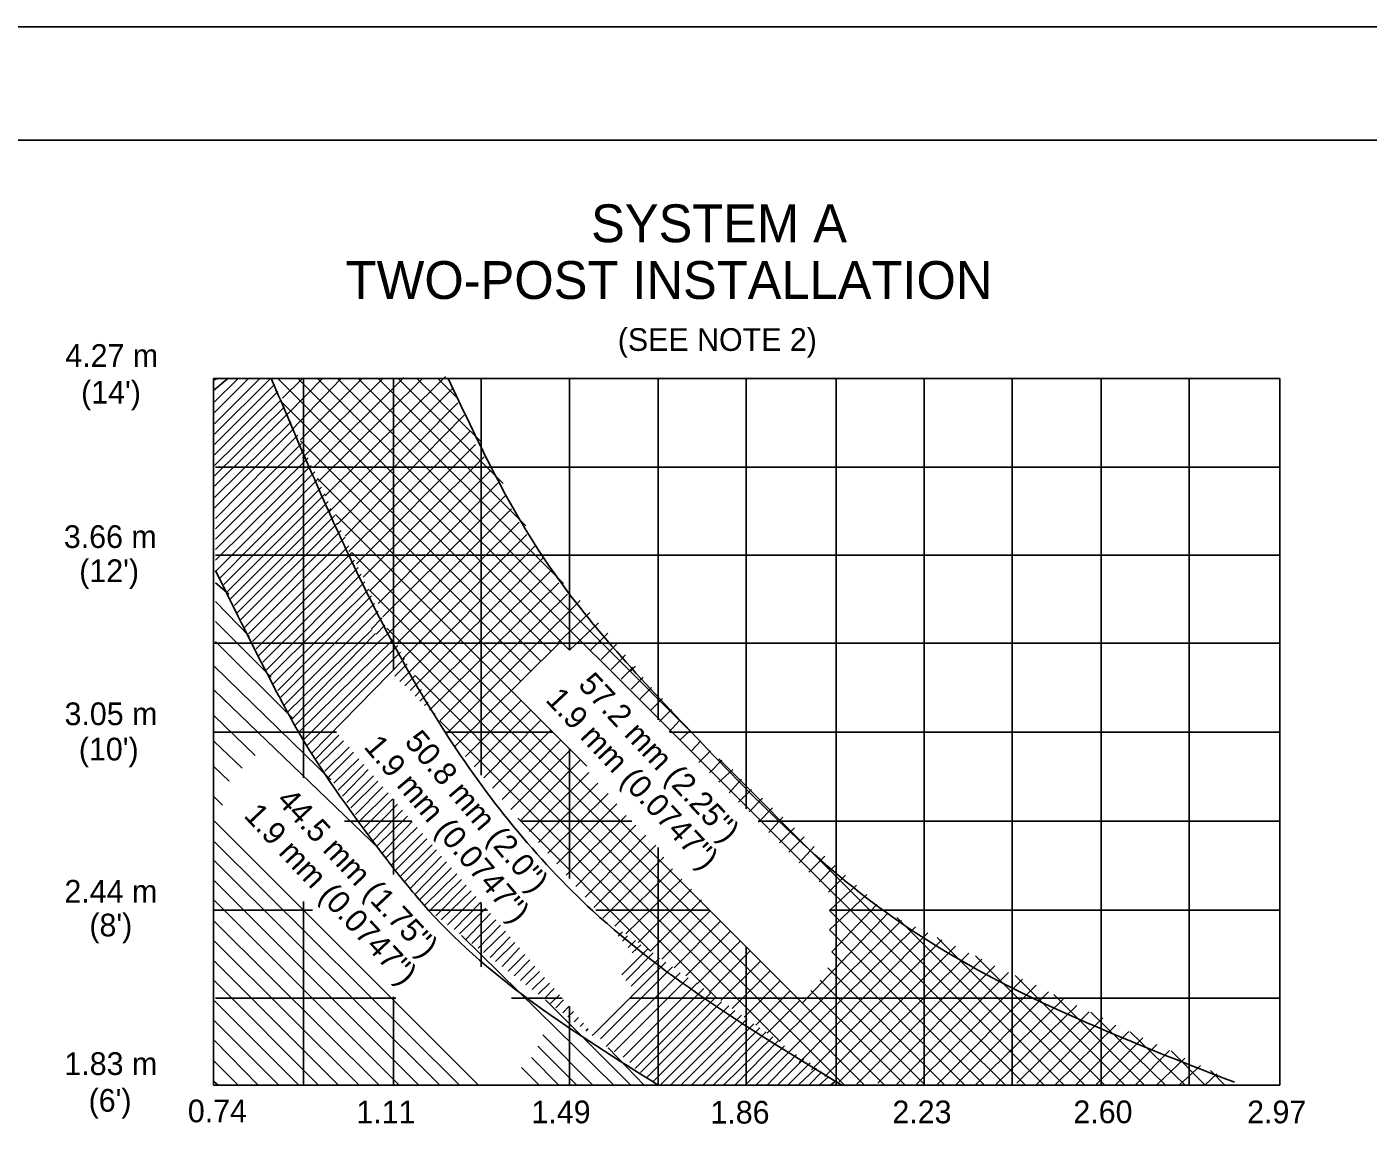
# Model space of a CAD drawing. Extents: x 644358 to 648627, y 294594 to 295782.
# Drawn here: x 645568.3 to 645745.5, y 295636.1 to 295781.6 of the extents above; entities that cross this region are included whole.
import ezdxf

# ---------------------------------------------------------------- set-up
doc = ezdxf.new("R2010")
doc.units = 0
for name, color, linetype in [('1', 7, 'Continuous'), ('10', 7, 'Continuous'), ('2', 7, 'Continuous'), ('4', 7, 'Continuous'), ('PLT-BNDY', 7, 'Continuous')]:
    doc.layers.add(name, color=color, linetype=linetype)

msp = doc.modelspace()

# ---------------------------------------------------------------- linework, layer by layer
at = {"layer": '1'}
msp.add_line((645239.31, 295766.63), (646025.31, 295766.63), dxfattribs=at)
at = {"layer": '10'}
for p, q in [((645592.94, 295734.93), (645593.44, 295735.18)), ((645592.94, 295733.56), (645594.81, 295735.18)), ((645593.06, 295732.06), (645596.19, 295735.18)), ((645593.06, 295730.68), (645597.56, 295735.18)), ((645593.06, 295729.18), (645599.06, 295735.18)), ((645593.06, 295727.81), (645600.44, 295735.18)), ((645637.51, 295699.12), (645601.44, 295735.18)), ((645602.06, 295732.56), (645604.69, 295735.18)), ((645602.69, 295730.43), (645607.31, 295735.18)), ((645603.31, 295728.43), (645609.69, 295735.06)), ((645639.97, 295699.28), (645604.06, 295735.18)), ((645604.44, 295727.06), (645612.56, 295735.18)), ((645604.69, 295724.68), (645615.31, 295735.18)), ((645606.19, 295723.43), (645618.06, 295735.31)), ((645650.65, 295691.28), (645606.69, 295735.18)), ((645606.81, 295721.56), (645620.56, 295735.18)), ((645607.69, 295719.68), (645623.56, 295735.43)), ((645655.79, 295688.71), (645609.31, 295735.18)), ((645639.19, 295708.06), (645612.06, 295735.18)), ((645634.19, 295715.68), (645614.69, 295735.18)), ((645631.19, 295721.31), (645617.31, 295735.18)), ((645628.31, 295726.81), (645619.81, 295735.18)), ((645625.31, 295732.43), (645622.56, 295735.18)), ((645593.06, 295726.43), (645600.94, 295734.31)), ((645593.06, 295725.06), (645601.44, 295733.43)), ((645608.19, 295717.56), (645624.44, 295733.81)), ((645593.06, 295723.68), (645601.81, 295732.31)), ((645593.06, 295722.31), (645602.31, 295731.43)), ((645636.19, 295697.81), (645602.06, 295731.93)), ((645609.31, 295715.93), (645625.19, 295731.93)), ((645593.06, 295720.93), (645602.81, 295730.56)), ((645593.06, 295719.43), (645603.19, 295729.43)), ((645610.31, 295714.31), (645626.06, 295730.31)), ((645593.06, 295718.06), (645603.56, 295728.56)), ((645593.19, 295716.68), (645604.06, 295727.68)), ((645610.81, 295712.31), (645626.81, 295728.18)), ((645593.19, 295715.31), (645604.56, 295726.56)), ((645593.19, 295713.93), (645604.94, 295725.68)), ((645634.87, 295696.5), (645604.44, 295726.93)), ((645611.81, 295710.68), (645627.56, 295726.43)), ((645593.19, 295712.56), (645605.44, 295724.68)), ((645612.69, 295708.93), (645628.69, 295724.81)), ((645593.19, 295711.18), (645605.81, 295723.68)), ((645593.19, 295709.68), (645606.31, 295722.81)), ((645613.69, 295707.18), (645629.56, 295723.06)), ((645593.81, 295708.81), (645606.69, 295721.81)), ((645594.31, 295707.93), (645607.19, 295720.81)), ((645633.51, 295695.16), (645606.69, 295721.93)), ((645614.69, 295705.43), (645630.56, 295721.43)), ((645594.69, 295706.93), (645607.69, 295719.93)), ((645595.19, 295706.06), (645608.06, 295718.93)), ((645615.31, 295703.68), (645631.44, 295719.68)), ((645595.69, 295705.18), (645608.44, 295717.93)), ((645596.06, 295704.18), (645608.94, 295717.06)), ((645642.24, 295683.95), (645609.06, 295717.18)), ((645615.81, 295701.31), (645632.31, 295717.93)), ((645596.56, 295703.31), (645609.31, 295716.06)), ((645597.06, 295702.31), (645609.81, 295715.06)), ((645617.19, 295700.18), (645633.31, 295716.18)), ((645597.56, 295701.43), (645610.31, 295714.18)), ((645617.53, 295695.15), (645635.56, 295713.18)), ((645617.94, 295698.18), (645634.31, 295714.56)), ((645598.06, 295700.43), (645610.81, 295713.06)), ((645598.56, 295699.43), (645611.19, 295712.18)), ((645681.56, 295641.81), (645611.19, 295712.18)), ((645618.92, 295693.92), (645636.44, 295711.43)), ((645598.94, 295698.56), (645611.56, 295711.18)), ((645599.44, 295697.68), (645612.06, 295710.18)), ((645620.17, 295692.55), (645637.56, 295709.81)), ((645594.94, 295706.68), (645593.19, 295708.18)), ((645599.94, 295696.68), (645612.44, 295709.31)), ((645600.31, 295695.81), (645612.94, 295708.31)), ((645621.46, 295691.34), (645638.56, 295708.18)), ((645600.81, 295694.81), (645613.44, 295707.31)), ((645601.44, 295693.93), (645613.81, 295706.43)), ((645678.94, 295641.81), (645613.56, 295707.18)), ((645633.14, 295700.18), (645639.69, 295706.68)), ((645597.69, 295701.06), (645593.19, 295705.68)), ((645601.81, 295693.06), (645614.19, 295705.43)), ((645602.31, 295692.06), (645614.69, 295704.43)), ((645635.69, 295700.18), (645641.35, 295705.84)), ((645600.56, 295695.68), (645593.19, 295703.06)), ((645613.81, 295702.1), (645615.19, 295703.56)), ((645614.4, 295701.4), (645615.56, 295702.56)), ((645638.36, 295700.18), (645642.63, 295704.23)), ((645639.97, 295699.28), (645643.79, 295702.89)), ((645602.81, 295691.18), (645613.87, 295702.02)), ((645603.31, 295690.18), (645614.35, 295701.46)), ((645615.06, 295700.62), (645616.06, 295701.56)), ((645676.31, 295641.81), (645615.81, 295702.18)), ((645642.71, 295699.21), (645645.02, 295701.51)), ((645603.44, 295690.18), (645593.19, 295700.43)), ((645603.69, 295689.31), (645615.03, 295700.65)), ((645604.19, 295688.43), (645616.7, 295700.7)), ((645604.81, 295687.43), (645617.26, 295699.88)), ((645605.31, 295686.68), (645617.64, 295699.01)), ((645622.81, 295689.93), (645633.14, 295700.18)), ((645623.81, 295688.31), (645635.69, 295700.18)), ((645624.81, 295686.56), (645638.59, 295700.18)), ((645644.16, 295698.05), (645645.76, 295699.65)), ((645645.31, 295699.18), (645646.19, 295700.06)), ((645608.43, 295682.12), (645592.94, 295697.23)), ((645605.94, 295685.68), (645618.16, 295698.15)), ((645616.9, 295695.84), (645618.52, 295697.46)), ((645645.47, 295696.73), (645647.08, 295698.34)), ((645646.63, 295697.87), (645647.37, 295698.66)), ((645618.19, 295694.55), (645619.57, 295695.93)), ((645667.75, 295647.63), (645619.57, 295695.93)), ((645646.79, 295695.42), (645648.39, 295697.02)), ((645648, 295696.5), (645648.67, 295697.17)), ((645648.1, 295694.11), (645649.7, 295695.71)), ((645593.02, 295694), (645614.84, 295672.96)), ((645619.55, 295693.19), (645620.41, 295694.06)), ((645649.2, 295692.73), (645650.81, 295694.33)), ((645620.8, 295691.95), (645621.27, 295692.42)), ((645626.23, 295685.23), (645633.56, 295692.64)), ((645650.65, 295691.28), (645652.26, 295692.88)), ((645593.02, 295690.58), (645598.42, 295685.37)), ((645622.03, 295690.72), (645622.22, 295690.91)), ((645627.38, 295683.87), (645634.85, 295691.35)), ((645700.19, 295641.81), (645650.65, 295691.28)), ((645651.85, 295689.84), (645653.44, 295691.43)), ((645659.44, 295653.31), (645622.81, 295689.93)), ((645628.64, 295682.39), (645636.18, 295690.02)), ((645629.79, 295681.04), (645637.48, 295688.72)), ((645653.11, 295688.49), (645654.44, 295689.93)), ((645654.54, 295687.39), (645655.81, 295688.56)), ((645593.02, 295687.22), (645596.71, 295683.66)), ((645606.44, 295684.93), (645609.49, 295688.05)), ((645606.98, 295684.23), (645610.12, 295687.3)), ((645631.05, 295679.55), (645638.81, 295687.39)), ((645656.02, 295685.91), (645657.31, 295687.31)), ((645607.65, 295683.28), (645610.84, 295686.46)), ((645608.17, 295682.55), (645611.41, 295685.78)), ((645608.82, 295681.69), (645612.13, 295684.93)), ((645632.2, 295678.2), (645640.1, 295686.1)), ((645657.06, 295684.43), (645658.61, 295685.98)), ((645702.69, 295641.81), (645659.69, 295684.93)), ((645593.02, 295683.85), (645594.99, 295681.95)), ((645609.41, 295680.78), (645612.79, 295684.16)), ((645609.98, 295679.98), (645613.35, 295683.5)), ((645633.46, 295676.71), (645641.43, 295684.76)), ((645634.67, 295675.29), (645642.5, 295683.12)), ((645658.44, 295683.06), (645660.1, 295684.73)), ((645659.69, 295681.81), (645661.53, 295683.48)), ((645610.53, 295679.15), (645614.05, 295682.67)), ((645611.06, 295678.43), (645614.66, 295681.95)), ((645635.87, 295673.87), (645643.69, 295681.69)), ((645661.06, 295680.43), (645662.7, 295682.23)), ((645593.02, 295679.87), (645594.12, 295678.8)), ((645611.67, 295677.54), (645615.31, 295681.19)), ((645612.24, 295676.73), (645615.99, 295680.4)), ((645612.83, 295675.83), (645616.63, 295679.63)), ((645637.08, 295672.45), (645645.05, 295680.34)), ((645662.31, 295679.18), (645664, 295680.88)), ((645663.69, 295677.93), (645665.46, 295679.71)), ((645613.43, 295675.06), (645617.22, 295678.94)), ((645614.02, 295674.14), (645617.91, 295678.13)), ((645638.28, 295671.03), (645646.21, 295678.95)), ((645664.94, 295676.56), (645666.8, 295678.42)), ((645627.94, 295641.81), (645593.06, 295676.68)), ((645614.54, 295673.41), (645618.58, 295677.35)), ((645615.24, 295672.49), (645619.18, 295676.64)), ((645650.66, 295659.49), (645633.15, 295677.07)), ((645639.54, 295669.54), (645647.44, 295677.44)), ((645640.81, 295668.06), (645648.74, 295676.14)), ((645666.31, 295675.18), (645668.16, 295677.21)), ((645615.71, 295671.83), (645619.84, 295675.86)), ((645616.38, 295670.88), (645620.54, 295675.04)), ((645616.92, 295670.17), (645621.11, 295674.36)), ((645642.01, 295666.64), (645650.05, 295674.83)), ((645667.69, 295673.81), (645669.68, 295675.8)), ((645668.94, 295672.56), (645670.98, 295674.6)), ((645625.44, 295641.81), (645593.06, 295673.93)), ((645617.61, 295669.36), (645621.8, 295673.55)), ((645618.17, 295668.67), (645622.37, 295672.87)), ((645643.16, 295665.28), (645651.38, 295673.5)), ((645670.31, 295671.18), (645672.29, 295673.34)), ((645622.81, 295641.81), (645593.06, 295671.43)), ((645618.91, 295667.78), (645623.07, 295672.05)), ((645619.55, 295667.04), (645623.7, 295671.31)), ((645644.37, 295663.86), (645652.42, 295671.92)), ((645671.56, 295669.93), (645673.69, 295672.06)), ((645672.94, 295668.68), (645675.07, 295670.82)), ((645620.16, 295666.29), (645624.38, 295670.51)), ((645620.79, 295665.54), (645625.06, 295669.7)), ((645621.56, 295664.93), (645625.69, 295668.96)), ((645645.93, 295662.8), (645653.59, 295670.39)), ((645647.4, 295661.77), (645654.79, 295669.01)), ((645674.19, 295667.31), (645676.41, 295669.54)), ((645620.06, 295641.81), (645593.06, 295668.81)), ((645622.31, 295664.18), (645626.33, 295668.21)), ((645623.01, 295663.63), (645626.96, 295667.48)), ((645649.02, 295660.64), (645656.09, 295667.71)), ((645674.3, 295664.89), (645677.88, 295668.21)), ((645617.44, 295641.81), (645593.06, 295666.18)), ((645623.86, 295662.98), (645627.6, 295666.72)), ((645624.71, 295662.34), (645628.24, 295665.96)), ((645650.63, 295659.51), (645657.42, 295666.29)), ((645674.3, 295662.32), (645679.23, 295666.97)), ((645674.6, 295659.39), (645680.56, 295665.68)), ((645625.43, 295661.78), (645628.91, 295665.18)), ((645626.32, 295661.1), (645629.52, 295664.46)), ((645627.06, 295660.53), (645630.22, 295663.63)), ((645652.17, 295658.43), (645658.53, 295664.84)), ((645670.72, 295652.65), (645682.06, 295664.56)), ((645671.81, 295651.56), (645683.83, 295663.57)), ((645697.56, 295641.81), (645674.3, 295664.89)), ((645705.31, 295641.81), (645683.19, 295663.93)), ((645614.81, 295641.81), (645593.06, 295663.43)), ((645627.88, 295659.9), (645630.83, 295662.92)), ((645628.62, 295659.34), (645631.49, 295662.14)), ((645646.37, 295661.5), (645646.95, 295662.07)), ((645653.79, 295657.3), (645659.9, 295663.47)), ((645655.33, 295656.22), (645661.21, 295662.16)), ((645673.09, 295650.28), (645685.66, 295662.7)), ((645694.81, 295641.81), (645674.3, 295662.32)), ((645674.42, 295648.95), (645687.28, 295661.91)), ((645612.19, 295641.81), (645593.06, 295660.81)), ((645645.81, 295641.81), (645625.69, 295661.59)), ((645629.5, 295658.67), (645632.11, 295661.41)), ((645630.17, 295658.15), (645632.75, 295660.65)), ((645646.95, 295660.82), (645647.64, 295661.51)), ((645648.67, 295660.89), (645647.69, 295659.98)), ((645648.25, 295659.29), (645649.39, 295660.34)), ((645656.82, 295655.18), (645662.53, 295660.84)), ((645671.94, 295643.81), (645689.13, 295661)), ((645673.69, 295642.93), (645690.94, 295660.18)), ((645708.06, 295641.81), (645688.55, 295661.32)), ((645631.05, 295657.48), (645633.37, 295659.92)), ((645631.86, 295656.86), (645634.08, 295659.08)), ((645632.64, 295656.26), (645634.71, 295658.34)), ((645646.87, 295656.37), (645650.34, 295659.84)), ((645647.39, 295655.64), (645651.01, 295659.26)), ((645648.12, 295654.87), (645651.83, 295658.58)), ((645658.42, 295654.06), (645663.84, 295659.53)), ((645692.19, 295641.81), (645674.6, 295659.39)), ((645675.56, 295642.18), (645692.74, 295659.22)), ((645677.94, 295641.93), (645694.43, 295658.43)), ((645710.69, 295641.81), (645693.62, 295658.88)), ((645609.44, 295641.81), (645593.06, 295658.18)), ((645633.49, 295655.61), (645635.4, 295657.53)), ((645634.21, 295655.05), (645636.01, 295656.81)), ((645643.14, 295648.51), (645652.68, 295658.05)), ((645644.04, 295647.92), (645653.56, 295657.43)), ((645644.82, 295646.89), (645654.58, 295656.65)), ((645659.97, 295652.97), (645665.19, 295658.18)), ((645661.43, 295651.92), (645666.47, 295656.9)), ((645689.56, 295641.81), (645674.08, 295657.29)), ((645680.69, 295642.06), (645696.17, 295657.55)), ((645683.19, 295641.93), (645697.95, 295656.7)), ((645606.81, 295641.81), (645593.06, 295655.56)), ((645635.04, 295654.42), (645636.67, 295656.04)), ((645635.82, 295653.82), (645637.3, 295655.29)), ((645645.85, 295646.21), (645655.62, 295655.98)), ((645647.05, 295645.48), (645656.82, 295655.25)), ((645663.04, 295650.79), (645667.81, 295655.56)), ((645686.94, 295641.81), (645673.06, 295655.67)), ((645685.81, 295641.93), (645699.82, 295655.8)), ((645688.56, 295641.93), (645701.62, 295654.99)), ((645713.31, 295641.81), (645698.82, 295656.3)), ((645604.19, 295641.81), (645593.06, 295652.93)), ((645636.6, 295653.22), (645637.93, 295654.55)), ((645648.06, 295641.81), (645636.8, 295653.07)), ((645637.45, 295652.57), (645638.62, 295653.74)), ((645638.16, 295652.03), (645639.19, 295653.06)), ((645647.93, 295644.81), (645657.7, 295654.57)), ((645648.63, 295644.01), (645658.58, 295653.95)), ((645649.34, 295643.46), (645659.33, 295653.46)), ((645664.59, 295649.71), (645669.12, 295654.25)), ((645666.07, 295648.68), (645670.4, 295652.97)), ((645684.31, 295641.81), (645671.85, 295654.3)), ((645690.94, 295641.81), (645703.24, 295654.11)), ((645693.56, 295641.81), (645705.19, 295653.14)), ((645715.94, 295641.81), (645703.96, 295653.79)), ((645639.06, 295651.34), (645639.91, 295652.22)), ((645639.74, 295650.82), (645640.48, 295651.54)), ((645650.19, 295642.81), (645660.06, 295652.82)), ((645650.94, 295642.18), (645661.03, 295652.27)), ((645651.94, 295641.81), (645661.8, 295651.67)), ((645667.68, 295647.55), (645671.75, 295651.62)), ((645696.31, 295641.93), (645707, 295652.32)), ((645699.06, 295642.06), (645708.62, 295651.47)), ((645718.69, 295641.81), (645708.82, 295651.45)), ((645601.56, 295641.81), (645593.06, 295650.31)), ((645640.59, 295650.17), (645641.17, 295650.73)), ((645641.39, 295649.55), (645641.81, 295649.98)), ((645653.31, 295641.81), (645662.7, 295651.06)), ((645654.69, 295641.81), (645663.45, 295650.57)), ((645656.06, 295641.81), (645664.31, 295649.91)), ((645657.56, 295641.81), (645665.1, 295649.35)), ((645668.31, 295645.56), (645673.09, 295650.28)), ((645701.56, 295641.81), (645710.44, 295650.68)), ((645704.06, 295641.81), (645712.15, 295649.74)), ((645598.81, 295641.81), (645593.06, 295647.68)), ((645643.06, 295641.81), (645636.45, 295648.45)), ((645642.14, 295648.98), (645642.43, 295649.25)), ((645642.97, 295648.34), (645643.09, 295648.47)), ((645658.94, 295641.81), (645665.94, 295648.82)), ((645660.31, 295641.81), (645666.82, 295648.16)), ((645661.81, 295641.81), (645667.51, 295647.65)), ((645670.31, 295644.81), (645674.42, 295648.95)), ((645706.81, 295641.81), (645713.87, 295648.87)), ((645709.44, 295641.81), (645715.69, 295648.06)), ((645721.31, 295641.81), (645714.05, 295648.84)), ((645640.94, 295641.81), (645635.79, 295646.96)), ((645649.83, 295641.81), (645645.08, 295646.73)), ((645663.19, 295641.81), (645668.38, 295647)), ((645666.06, 295641.81), (645669.96, 295645.86)), ((645712.06, 295641.81), (645717.57, 295647.15)), ((645714.72, 295641.84), (645719.25, 295646.37)), ((645719.44, 295646.31), (645723.94, 295641.81)), ((645596.19, 295641.81), (645592.94, 295645.06)), ((645635.94, 295641.81), (645633.62, 295644.12)), ((645638.56, 295641.81), (645634.93, 295645.44)), ((645664.56, 295641.81), (645668.44, 295645.68)), ((645667.44, 295641.81), (645670.9, 295645.27)), ((645668.81, 295641.81), (645671.75, 295644.75)), ((645670.19, 295641.81), (645672.56, 295644.04)), ((645717.57, 295641.83), (645721.27, 295645.35)), ((645720.57, 295641.83), (645723.32, 295644.4)), ((645593.56, 295641.81), (645592.94, 295642.31)), ((645671.56, 295641.81), (645673.31, 295643.56)), ((645672.94, 295641.81), (645674.22, 295642.93)), ((645674.44, 295641.81), (645675.16, 295642.35)), ((645723.9, 295641.81), (645725.5, 295643.3)), ((645726.56, 295641.81), (645724.64, 295643.73)), ((645675.81, 295641.81), (645675.81, 295641.81))]:
    msp.add_line(p, q, dxfattribs=at)
at = {"layer": '2'}
for p, q in [((645733.81, 295735.18), (645592.94, 295735.18)), ((645592.94, 295688.43), (645592.94, 295735.18)), ((645604.81, 295682.41), (645604.81, 295735.18)), ((645616.69, 295696.65), (645616.69, 295735.18)), ((645628.31, 295682.77), (645628.31, 295735.18)), ((645639.94, 295699.31), (645639.94, 295735.18)), ((645651.69, 295690.07), (645651.69, 295735.18)), ((645663.31, 295678.29), (645663.31, 295735.18)), ((645675.19, 295641.81), (645675.19, 295735.18)), ((645686.81, 295641.81), (645686.81, 295735.18)), ((645698.44, 295641.81), (645698.44, 295735.18)), ((645710.19, 295641.81), (645710.19, 295735.18)), ((645721.81, 295641.81), (645721.81, 295735.18)), ((645733.81, 295641.81), (645733.81, 295735.18)), ((645733.69, 295723.43), (645593.19, 295723.43)), ((645733.69, 295711.81), (645593.19, 295711.81)), ((645644.31, 295700.18), (645592.94, 295700.18)), ((645733.69, 295700.18), (645641.73, 295700.18)), ((645592.94, 295641.81), (645592.94, 295688.43)), ((645609.16, 295688.43), (645592.94, 295688.43)), ((645637.76, 295688.43), (645623.51, 295688.43)), ((645733.69, 295688.43), (645653.21, 295688.43)), ((645639.94, 295669.08), (645639.94, 295686.26)), ((645616.69, 295669.63), (645616.69, 295679.57)), ((645619.14, 295676.68), (645610.22, 295676.68)), ((645648.2, 295676.68), (645633.48, 295676.68)), ((645733.69, 295676.68), (645664.87, 295676.68)), ((645651.69, 295653.31), (645651.69, 295673.19)), ((645604.81, 295641.81), (645604.81, 295666.06)), ((645628.31, 295657.43), (645628.31, 295665.88)), ((645606, 295664.93), (645592.94, 295664.93)), ((645629.11, 295664.93), (645621.32, 295664.93)), ((645658.44, 295664.93), (645643.46, 295664.93)), ((645733.69, 295664.93), (645674.3, 295664.93)), ((645663.31, 295641.81), (645663.31, 295660.06)), ((645617, 295653.31), (645593.19, 295653.31)), ((645638.98, 295653.31), (645632.28, 295653.31)), ((645733.78, 295653.31), (645647.94, 295653.31)), ((645651.69, 295641.81), (645651.69, 295653.31)), ((645639.94, 295641.81), (645639.94, 295652.19)), ((645639.94, 295641.81), (645592.94, 295641.81)), ((645733.81, 295641.81), (645639.94, 295641.81))]:
    msp.add_line(p, q, dxfattribs=at)
at = {"layer": '4'}
for p, q in [((645600.94, 295735.18), (645600.94, 295735.18)), ((645623.94, 295735.18), (645623.94, 295735.18)), ((645610.81, 295711.81), (645610.81, 295711.81)), ((645636.31, 295711.81), (645636.31, 295711.81)), ((645623.44, 295688.56), (645623.44, 295688.56)), ((645655.94, 295688.56), (645655.94, 295688.56)), ((645643.06, 295664.81), (645643.06, 295664.81)), ((645681.69, 295664.68), (645681.69, 295664.68)), ((645616.69, 295641.81), (645616.69, 295653.45)), ((645676.06, 295641.81), (645676.06, 295641.81)), ((645728.19, 295641.81), (645728.19, 295641.81))]:
    msp.add_line(p, q, dxfattribs=at)
for points in [[(645675.94, 295641.81), (645643.06, 295664.81), (645623.44, 295688.56), (645610.81, 295711.81), (645600.56, 295735.18)], [(645727.81, 295642.18), (645681.69, 295664.68), (645655.94, 295688.56), (645636.31, 295711.81), (645623.94, 295735.18)], [(645616.6, 295670.57), (645604.69, 295687.56), (645601.31, 295693.68), (645593.19, 295709.81)], [(645651.69, 295641.81), (645621.31, 295664.93), (645616.6, 295670.57)]]:
    msp.add_spline(points, degree=3, dxfattribs=at)
at = {"layer": 'PLT-BNDY'}
msp.add_lwpolyline([(645199.31, 295781.63), (646040.31, 295781.63), (646040.31, 295187.63), (645199.31, 295187.63)], close=True, dxfattribs=at)

# ---------------------------------------------------------------- texts
at = {"layer": '4'}
for s, height, p in [('SYSTEM A', 5, (645642.81, 295753.17)), ('TWO-POST INSTALLATION', 5, (645610.39, 295745.67)), ('(SEE NOTE 2)', 3, (645646.34, 295738.81)), ('4.27 m', 3, (645573.35, 295736.7)), ("(14')", 3, (645575.44, 295731.85)), ('3.66 m', 3, (645573.16, 295712.77)), ("(12')", 3, (645575.19, 295708.26)), ('3.05 m', 3, (645573.25, 295689.36)), ("(10')", 3, (645575.14, 295684.7)), ('2.44 m', 3, (645573.24, 295665.91)), ("(8')", 3, (645576.53, 295661.45)), ('1.83 m', 3, (645573.23, 295643.14)), ("(6')", 3, (645576.43, 295638.29)), ('0.74', 3, (645589.54, 295636.89)), ('1.11', 3, (645611.8, 295636.75)), ('1.49', 3, (645634.94, 295636.76)), ('1.86', 3, (645658.58, 295636.72)), ('2.23', 3, (645682.62, 295636.76)), ('2.60', 3, (645706.53, 295636.77)), ('2.97', 3, (645729.49, 295636.76))]:
    msp.add_text(s, height=height, dxfattribs=at).set_placement(p)
for s, rotation, p in [('57.2 mm (2.25")', 313, (645640.98, 295694.58)), ('1.9 mm (0.0747")', 313, (645636.67, 295692.61)), ('50.8 mm (2.0")', 310.3915, (645618.05, 295687.09)), ('1.9 mm (0.0747")', 310.3915, (645612.67, 295686.46)), ('44.5 mm (1.75")', 313.1129, (645601.13, 295679.3)), ('1.9 mm (0.0747")', 313.1129, (645596.82, 295677.32))]:
    msp.add_text(s, height=3, rotation=rotation, dxfattribs=at).set_placement(p)

doc.saveas('drawing.dxf')
